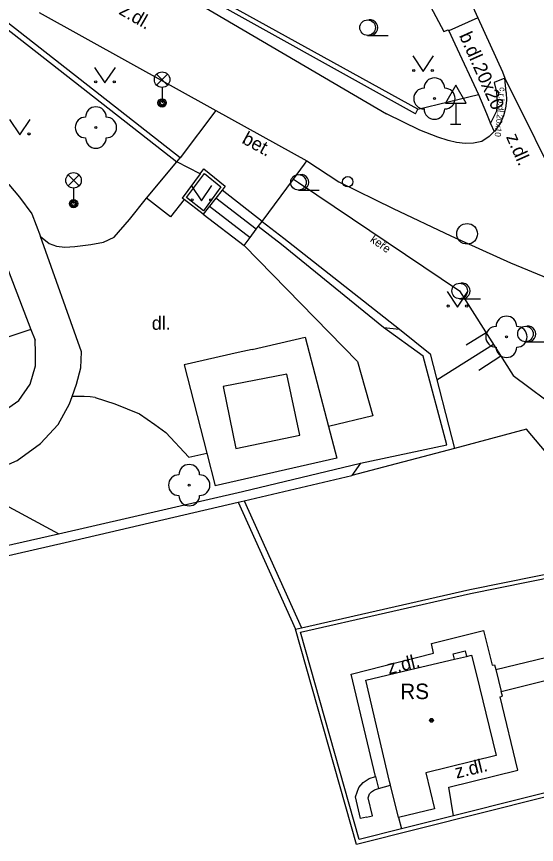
# Model space of a CAD drawing. Extents: x -595546 to -593986, y -1160845 to -1159202.
# Drawn here: x -595356.89 to -595331.77, y -1160440.78 to -1160400.75 of the extents above; entities that cross this region are included whole.
import ezdxf

# ---------------------------------------------------------------- set-up
doc = ezdxf.new("R2010")
doc.units = 0
for name, color, linetype in [('Level 22', 7, 'Continuous'), ('Level 27', 7, 'Continuous'), ('Level 31', 7, 'Continuous'), ('Level 33', 7, 'Continuous'), ('Level 34', 7, 'Continuous'), ('Level 36', 7, 'Continuous'), ('Level 39', 7, 'Continuous'), ('silnoproud - povrch.  znaky a  RIS  skut. velikost', 7, 'Continuous'), ('Specificka linie pasportu komunikaci', 7, 'Continuous'), ('TM - budovy zdene_ betonove - VP', 7, 'Continuous'), ('TM - chodniky - VP', 7, 'Continuous'), ('TM - horni hrana svahu', 7, 'Continuous'), ('TM - komunikace - VP', 7, 'Continuous'), ('TM - plot drateny_ kovovy - VP', 7, 'Continuous'), ('TM - plot dreveny - VP', 7, 'Continuous'), ('TM - plot zivy - VP', 7, 'Continuous'), ('TM - podezdivka plotu - VP', 7, 'Continuous'), ('TM - pomocna konstrukcni linie', 7, 'Continuous'), ('TM - popis objektu', 7, 'Continuous'), ('TM - popis povrchu', 7, 'Continuous'), ('TM - popis zelene', 7, 'Continuous'), ('TM - rozhrani mezi zpev. plochami mezi sebou - VP', 7, 'Continuous'), ('TM - rozhrani ploch obecne - VP', 7, 'Continuous'), ('TM - schody - VP', 7, 'Continuous'), ('TM - srafovani', 7, 'Continuous'), ('TM - zed operna - VP', 7, 'Continuous')]:
    doc.layers.add(name, color=color, linetype=linetype)

msp = doc.modelspace()

# ---------------------------------------------------------------- linework, layer by layer
at = {"layer": 'Level 22'}
for centre in [(-595336.7, -1160404.72), (-595353.06, -1160406.12), (-595333.22, -1160416.24), (-595348.55, -1160423.41)]:
    msp.add_circle(centre, 0.05, dxfattribs=at)
for centre, start, end in [((-595336.7, -1160404.22), 0, 180), ((-595337.2, -1160404.72), 90, 270), ((-595336.2, -1160404.72), 270, 90), ((-595353.06, -1160405.62), 0, 180), ((-595336.7, -1160405.22), 180, 0), ((-595353.56, -1160406.12), 90, 270), ((-595352.56, -1160406.12), 270, 90), ((-595353.06, -1160406.62), 180, 0), ((-595333.22, -1160415.74), 0, 180), ((-595333.72, -1160416.24), 90, 270), ((-595332.72, -1160416.24), 270, 90), ((-595333.22, -1160416.74), 180, 0), ((-595348.55, -1160422.91), 0, 180), ((-595349.05, -1160423.41), 90, 270), ((-595348.05, -1160423.41), 270, 90), ((-595348.55, -1160423.91), 180, 0)]:
    msp.add_arc(centre, 0.5, start, end, dxfattribs=at)
at = {"layer": 'Level 27'}
msp.add_circle((-595335.12, -1160411.26), 0.5, dxfattribs=at)
at = {"layer": 'Level 31'}
msp.add_circle((-595340.89, -1160408.74), 0.25, dxfattribs=at)
at = {"layer": 'Level 33'}
for p, q in [((-595350.125, -1160404.07), (-595349.595, -1160403.54)), ((-595350.125, -1160403.54), (-595349.595, -1160404.07)), ((-595349.86, -1160404.18), (-595349.86, -1160404.93)), ((-595354.405, -1160408.94), (-595353.875, -1160408.41)), ((-595354.405, -1160408.41), (-595353.875, -1160408.94)), ((-595354.14, -1160409.05), (-595354.14, -1160409.8))]:
    msp.add_line(p, q, dxfattribs=at)
for centre, radius in [((-595349.86, -1160403.805), 0.375), ((-595349.86, -1160404.93), 0.2), ((-595349.86, -1160404.93), 0.145), ((-595349.86, -1160404.93), 0.0876), ((-595354.14, -1160408.675), 0.375), ((-595354.14, -1160409.8), 0.2), ((-595354.14, -1160409.8), 0.145), ((-595354.14, -1160409.8), 0.0876)]:
    msp.add_circle(centre, radius, dxfattribs=at)
at = {"layer": 'Level 34'}
for p, q in [((-595335.67, -1160404.942), (-595335.67, -1160405.96)), ((-595335.92, -1160405.96), (-595335.42, -1160405.96))]:
    msp.add_line(p, q, dxfattribs=at)
msp.add_lwpolyline([(-595336.17, -1160404.942), (-595335.17, -1160404.942), (-595335.67, -1160404.076)], close=True, dxfattribs=at)
at = {"layer": 'Level 36'}
for p, q in [((-595339.93, -1160401.665), (-595338.93, -1160401.665)), ((-595343.27, -1160409.145), (-595342.27, -1160409.145)), ((-595335.48, -1160414.395), (-595334.48, -1160414.395)), ((-595332.3, -1160416.475), (-595331.3, -1160416.475))]:
    msp.add_line(p, q, dxfattribs=at)
for points in [[(-595337.75, -1160402.66), (-595337.25, -1160403.41), (-595336.75, -1160402.66)], [(-595353.12, -1160403.21), (-595352.62, -1160403.96), (-595352.12, -1160403.21)], [(-595357.24, -1160405.73), (-595356.74, -1160406.48), (-595356.24, -1160405.73)], [(-595348.46, -1160408.92), (-595347.96, -1160409.67), (-595347.46, -1160408.92)], [(-595336.09, -1160414.05), (-595335.59, -1160414.8), (-595335.09, -1160414.05)]]:
    msp.add_lwpolyline(points, dxfattribs=at)
for centre, radius in [((-595339.93, -1160401.29), 0.375), ((-595337.7, -1160403.36), 0.05), ((-595336.801, -1160403.36), 0.05), ((-595353.07, -1160403.91), 0.05), ((-595352.171, -1160403.91), 0.05), ((-595356.291, -1160406.43), 0.05), ((-595343.27, -1160408.77), 0.375), ((-595348.41, -1160409.62), 0.05), ((-595347.511, -1160409.62), 0.05), ((-595335.48, -1160414.02), 0.375), ((-595336.04, -1160414.75), 0.05), ((-595335.141, -1160414.75), 0.05), ((-595332.3, -1160416.1), 0.375)]:
    msp.add_circle(centre, radius, dxfattribs=at)
for centre in [(-595339.805, -1160401.29), (-595343.145, -1160408.77), (-595335.355, -1160414.02), (-595332.175, -1160416.1)]:
    msp.add_arc(centre, 0.375, 260.4059, 99.5941, dxfattribs=at)
at = {"layer": 'Level 39'}
for radius in [0.09, 0.0398]:
    msp.add_circle((-595336.84, -1160434.78), radius, dxfattribs=at)
at = {"layer": 'silnoproud - povrch.  znaky a  RIS  skut. velikost'}
msp.add_lwpolyline([(-595335.73, -1160431.83), (-595335.8, -1160431.57), (-595335.22, -1160431.42), (-595335.15, -1160431.69)], dxfattribs=at)
at = {"layer": 'Specificka linie pasportu komunikaci'}
for points in [[(-595348.02, -1160408.36), (-595349.15, -1160407.78)], [(-595339.16, -1160415.79), (-595338.39, -1160415.87)], [(-595353.1, -1160419.17), (-595353.34, -1160419.14), (-595353.62, -1160419.12), (-595353.8, -1160419.12), (-595354.03, -1160419.12), (-595354.21, -1160419.13)], [(-595340.28, -1160422.35), (-595340.69, -1160422.95)]]:
    msp.add_lwpolyline(points, dxfattribs=at)
at = {"layer": 'TM - budovy zdene_ betonove - VP'}
for points in [[(-595337.58, -1160432.26), (-595335.73, -1160431.83)], [(-595335.73, -1160431.83), (-595335.15, -1160431.69)], [(-595335.15, -1160431.69), (-595334.9, -1160431.63)], [(-595334.9, -1160431.63), (-595334.67, -1160432.58)], [(-595340.01, -1160432.83), (-595337.58, -1160432.26)], [(-595334.67, -1160432.58), (-595334.22, -1160434.44)], [(-595338.87, -1160437.73), (-595340.01, -1160432.83)], [(-595334.22, -1160434.44), (-595333.72, -1160436.48)], [(-595333.72, -1160436.48), (-595337.12, -1160437.31)], [(-595337.12, -1160437.31), (-595336.7, -1160439.06)], [(-595338.82, -1160437.92), (-595338.87, -1160437.73)], [(-595338.44, -1160439.48), (-595338.82, -1160437.92)], [(-595336.7, -1160439.06), (-595338.44, -1160439.48)]]:
    msp.add_lwpolyline(points, dxfattribs=at)
at = {"layer": 'TM - chodniky - VP'}
for points in [[(-595337.02, -1160400.02), (-595336.24, -1160401.47)], [(-595336.24, -1160401.47), (-595336.04, -1160401.4), (-595336, -1160401.44)], [(-595336, -1160401.44), (-595335.71, -1160402.08)], [(-595335.71, -1160402.08), (-595334.57, -1160404.53)], [(-595334.57, -1160404.53), (-595334.19, -1160405.44)], [(-595347.27, -1160405.29), (-595348.98, -1160407.58)], [(-595334.19, -1160405.44), (-595333.99, -1160405.93)], [(-595333.99, -1160405.93), (-595333.81, -1160406.31)], [(-595364.23, -1160407.36), (-595363.06, -1160407.11), (-595361.66, -1160407.04), (-595360.33, -1160407.21), (-595359.14, -1160407.65), (-595358.12, -1160408.2), (-595357.26, -1160408.88), (-595356.75, -1160409.49), (-595356.15, -1160410.29)], [(-595349.15, -1160407.78), (-595348.98, -1160407.58)], [(-595350.61, -1160409.54), (-595349.15, -1160407.78)], [(-595343.51, -1160408.61), (-595342.98, -1160407.89), (-595342.86, -1160407.73)], [(-595345.03, -1160410.66), (-595343.51, -1160408.61)], [(-595355.74, -1160411.39), (-595355.31, -1160411.72), (-595354.96, -1160411.86), (-595354.56, -1160411.9), (-595354.08, -1160411.87), (-595353.31, -1160411.78), (-595352.69, -1160411.66), (-595352.17, -1160411.42), (-595351.44, -1160410.56), (-595350.61, -1160409.54)], [(-595356.15, -1160410.29), (-595355.74, -1160411.39)], [(-595345.21, -1160410.9), (-595345.03, -1160410.66)], [(-595345.89, -1160411.82), (-595345.6, -1160411.43), (-595345.32, -1160411.04), (-595345.21, -1160410.9)], [(-595357.87, -1160411.58), (-595356.2, -1160415.88)], [(-595340.41, -1160417.43), (-595345.89, -1160411.82)], [(-595356.2, -1160415.88), (-595356, -1160416.4)], [(-595358.52, -1160420.22), (-595357.64, -1160419.92), (-595356.79, -1160419.31), (-595356.24, -1160418.52), (-595355.97, -1160417.64), (-595355.97, -1160416.99), (-595356, -1160416.4)], [(-595354.21, -1160419.13), (-595353.99, -1160418.52), (-595353.79, -1160417.74), (-595353.75, -1160416.97)], [(-595340.41, -1160417.43), (-595339.67, -1160420.06), (-595341.82, -1160420.57)], [(-595358.01, -1160422.72), (-595356.86, -1160422.21), (-595355.73, -1160421.39), (-595354.88, -1160420.47), (-595354.33, -1160419.48), (-595354.21, -1160419.13)], [(-595353.1, -1160419.17), (-595352.15, -1160419.48), (-595350.96, -1160419.96), (-595350.21, -1160420.47), (-595349.68, -1160420.87)], [(-595349.68, -1160420.87), (-595348.57, -1160422.06)], [(-595348.57, -1160422.06), (-595347.7, -1160421.87)]]:
    msp.add_lwpolyline(points, dxfattribs=at)
at = {"layer": 'TM - horni hrana svahu'}
for points in [[(-595343.51, -1160408.61), (-595343.27, -1160408.77)], [(-595335.48, -1160414.02), (-595332.9, -1160418.11)], [(-595332.9, -1160418.11), (-595330.56, -1160419.85)]]:
    msp.add_lwpolyline(points, dxfattribs=at)
at = {"layer": 'TM - komunikace - VP'}
for points in [[(-595337.63, -1160394.11), (-595334.6, -1160400.82)], [(-595348.94, -1160399.63), (-595339.02, -1160405.46)], [(-595355.8, -1160400.56), (-595347.27, -1160405.29)], [(-595334.6, -1160400.82), (-595333.41, -1160403.42), (-595333.29, -1160403.74)], [(-595333.24, -1160404.43), (-595333.29, -1160403.74)], [(-595333.24, -1160404.43), (-595333.22, -1160404.81), (-595333.26, -1160405.18), (-595333.36, -1160405.55), (-595333.51, -1160405.89)], [(-595347.27, -1160405.29), (-595342.86, -1160407.73)], [(-595337.4, -1160406.25), (-595339.02, -1160405.46)], [(-595333.51, -1160405.89), (-595333.75, -1160406.25), (-595333.81, -1160406.31)], [(-595336.54, -1160406.58), (-595337.4, -1160406.25)], [(-595333.81, -1160406.31), (-595334.06, -1160406.55), (-595334.41, -1160406.8)], [(-595336.03, -1160406.74), (-595336.54, -1160406.58)], [(-595334.41, -1160406.8), (-595334.81, -1160406.88), (-595335.22, -1160406.9), (-595335.63, -1160406.85), (-595336.03, -1160406.74)], [(-595342.86, -1160407.73), (-595341.32, -1160408.75)], [(-595341.32, -1160408.75), (-595338.69, -1160410.04)], [(-595338.69, -1160410.04), (-595335.9, -1160411.35)], [(-595335.9, -1160411.35), (-595333.03, -1160412.66)], [(-595333.03, -1160412.66), (-595331.18, -1160413.42)]]:
    msp.add_lwpolyline(points, dxfattribs=at)
at = {"layer": 'TM - plot drateny_ kovovy - VP'}
for points in [[(-595337.62, -1160405.46), (-595337.5, -1160405.24), (-595348.43, -1160399.19), (-595348.52, -1160398.84)], [(-595332.25, -1160420.71), (-595335.73, -1160421.63)], [(-595328.52, -1160425.14), (-595332.25, -1160420.71)], [(-595335.73, -1160421.63), (-595340.69, -1160422.95)], [(-595345.9, -1160424.17), (-595340.69, -1160422.95)], [(-595403.749, -1160437.257), (-595380.44, -1160432.07), (-595370.02, -1160429.73), (-595354.55, -1160426.18), (-595346.18, -1160424.24)], [(-595346.18, -1160424.24), (-595345.9, -1160424.17)], [(-595346.18, -1160424.24), (-595343.42, -1160430.37)], [(-595334.95, -1160428.65), (-595326.59, -1160426.96)], [(-595343.17, -1160430.52), (-595334.95, -1160428.65)], [(-595340.33, -1160440.54), (-595343.17, -1160430.52)], [(-595325.46, -1160436.8), (-595335.78, -1160439.39)], [(-595335.78, -1160439.39), (-595338.29, -1160440.03)], [(-595338.29, -1160440.03), (-595340.33, -1160440.54)]]:
    msp.add_lwpolyline(points, dxfattribs=at)
at = {"layer": 'TM - plot dreveny - VP'}
for points in [[(-595345.51, -1160416.85), (-595342.95, -1160416.26), (-595341.82, -1160420.57)], [(-595346.19, -1160417), (-595348.79, -1160417.6), (-595347.7, -1160421.87)], [(-595345.51, -1160416.85), (-595346.19, -1160417)], [(-595341.82, -1160420.57), (-595341.42, -1160422.1)], [(-595347.7, -1160421.87), (-595347.3, -1160423.44)], [(-595341.42, -1160422.1), (-595347.3, -1160423.44)]]:
    msp.add_lwpolyline(points, dxfattribs=at)
at = {"layer": 'TM - plot zivy - VP'}
msp.add_lwpolyline([(-595343.27, -1160408.77), (-595335.48, -1160414.02)], dxfattribs=at)
at = {"layer": 'TM - podezdivka plotu - VP'}
for points in [[(-595337.62, -1160405.46), (-595348.6, -1160399.33)], [(-595348.02, -1160408.36), (-595348.89, -1160409.53)], [(-595348.02, -1160408.36), (-595347.84, -1160408.12), (-595346.81, -1160408.95), (-595346.96, -1160409.15)], [(-595346.96, -1160409.15), (-595347.27, -1160409.54), (-595347.57, -1160409.92), (-595347.87, -1160410.31)], [(-595348.8, -1160409.6), (-595348.89, -1160409.53)], [(-595347.87, -1160410.31), (-595348.8, -1160409.6)], [(-595339.16, -1160415.79), (-595344.09, -1160411.77), (-595345.21, -1160410.9)], [(-595354.86, -1160425.77), (-595345.98, -1160423.72), (-595340.28, -1160422.35)], [(-595345.9, -1160424.17), (-595343.12, -1160430.3)], [(-595379.73, -1160431.39), (-595354.86, -1160425.77)], [(-595334.99, -1160428.45), (-595326.77, -1160426.79)], [(-595343.12, -1160430.3), (-595334.99, -1160428.45)], [(-595343.42, -1160430.37), (-595343.12, -1160430.3)], [(-595340.47, -1160440.78), (-595343.42, -1160430.37)], [(-595325.41, -1160436.99), (-595340.47, -1160440.78)]]:
    msp.add_lwpolyline(points, dxfattribs=at)
at = {"layer": 'TM - pomocna konstrukcni linie'}
for points in [[(-595337.5, -1160405.24), (-595334.57, -1160404.53)], [(-595338.44, -1160439.48), (-595338.29, -1160440.03)]]:
    msp.add_lwpolyline(points, dxfattribs=at)
at = {"layer": 'TM - rozhrani mezi zpev. plochami mezi sebou - VP'}
for points in [[(-595334.6, -1160400.82), (-595336, -1160401.44)], [(-595333.29, -1160403.74), (-595333.81, -1160403.95)], [(-595333.81, -1160403.95), (-595333.7, -1160404.41), (-595333.66, -1160404.87), (-595333.7, -1160405.34)], [(-595333.29, -1160403.74), (-595330.38, -1160409.6)], [(-595333.99, -1160405.93), (-595333.7, -1160405.34)], [(-595333.73, -1160432.32), (-595333.47, -1160433.38)], [(-595339.54, -1160437.5), (-595339.4, -1160438.08)]]:
    msp.add_lwpolyline(points, dxfattribs=at)
at = {"layer": 'TM - rozhrani ploch obecne - VP'}
for points in [[(-595348.98, -1160407.58), (-595357.7, -1160400.77), (-595365.59, -1160402.81), (-595365.53, -1160403.05), (-595357.76, -1160401.04), (-595349.15, -1160407.78)], [(-595345.03, -1160410.66), (-595346.96, -1160409.15)], [(-595348.8, -1160409.6), (-595349.46, -1160410.44), (-595350.61, -1160409.54)], [(-595347.87, -1160410.31), (-595345.89, -1160411.82)], [(-595345.03, -1160410.66), (-595343.98, -1160411.47), (-595338.39, -1160415.87)], [(-595356.2, -1160415.88), (-595362.47, -1160417.98), (-595363.77, -1160412.99), (-595359.54, -1160411.59), (-595357.87, -1160411.58)], [(-595353.75, -1160416.97), (-595355.74, -1160411.39)], [(-595338.39, -1160415.87), (-595336.91, -1160417.06)], [(-595336.91, -1160417.06), (-595335.73, -1160421.63)], [(-595343.84, -1160418.05), (-595346.91, -1160418.64)], [(-595343.2, -1160421), (-595343.84, -1160418.05)], [(-595346.91, -1160418.64), (-595346.3, -1160421.63)], [(-595346.3, -1160421.63), (-595343.2, -1160421)], [(-595354.86, -1160425.77), (-595358.04, -1160424.05), (-595369.83, -1160427.07), (-595380.2, -1160429.3), (-595379.73, -1160431.39)], [(-595340.73, -1160432.55), (-595336.75, -1160431.54), (-595336.84, -1160431.06), (-595334.33, -1160430.43), (-595333.91, -1160432.12)], [(-595333.73, -1160432.32), (-595326.34, -1160430.53)], [(-595333.47, -1160433.38), (-595325.61, -1160431.42)], [(-595333.91, -1160432.12), (-595333.8, -1160432.09), (-595333.73, -1160432.32)], [(-595339.54, -1160437.5), (-595340.73, -1160432.55)], [(-595335.78, -1160439.39), (-595336.01, -1160438.01), (-595332.67, -1160437.19), (-595333.53, -1160433.64), (-595333.41, -1160433.61)], [(-595333.41, -1160433.61), (-595333.47, -1160433.38)], [(-595339.99, -1160439.46), (-595340.28, -1160439.53), (-595340.52, -1160438.48), (-595340.35, -1160438.03), (-595340.14, -1160437.78), (-595339.85, -1160437.59), (-595339.54, -1160437.5)], [(-595339.4, -1160438.08), (-595338.82, -1160437.92)], [(-595339.99, -1160439.46), (-595339.7, -1160439.39), (-595339.9, -1160438.52), (-595339.83, -1160438.34), (-595339.74, -1160438.24), (-595339.59, -1160438.14), (-595339.4, -1160438.08)]]:
    msp.add_lwpolyline(points, dxfattribs=at)
at = {"layer": 'TM - schody - VP'}
for points in [[(-595345.32, -1160411.04), (-595347.27, -1160409.54)], [(-595347.57, -1160409.92), (-595345.6, -1160411.43)]]:
    msp.add_lwpolyline(points, dxfattribs=at)
at = {"layer": 'TM - srafovani'}
for points in [[(-595334.2, -1160416.05), (-595335.16, -1160416.65)], [(-595333.84, -1160416.61), (-595336.58, -1160418.34)], [(-595333.49, -1160417.18), (-595334.56, -1160417.86)]]:
    msp.add_lwpolyline(points, dxfattribs=at)
at = {"layer": 'TM - zed operna - VP'}
for points in [[(-595348.68, -1160409.5), (-595347.81, -1160408.34), (-595347.02, -1160408.98)], [(-595347.02, -1160408.98), (-595347.86, -1160410.14), (-595348.68, -1160409.5)], [(-595337.25, -1160417.18), (-595339.16, -1160415.79)], [(-595336.1, -1160421.46), (-595337.25, -1160417.18)], [(-595340.28, -1160422.35), (-595336.1, -1160421.46)]]:
    msp.add_lwpolyline(points, dxfattribs=at)

# ---------------------------------------------------------------- texts
at = {"layer": 'TM - popis objektu'}
msp.add_text('RS', height=0.75, rotation=0.34, dxfattribs=at).set_placement((-595338.35, -1160433.76))
at = {"layer": 'TM - popis povrchu'}
for s, height, rotation, p in [('z.dl.', 0.65, 330.0258, (-595351.99, -1160400.61)), ('b.dl.20x20', 0.65, 294.0584, (-595335.52, -1160401.67)), ('č.r.b.dl.20x10', 0.3, 264, (-595333.54, -1160404.16)), ('bet.', 0.65, 331.4456, (-595346.05, -1160406.85)), ('z.dl.', 0.65, 293.9123, (-595333.25, -1160406.57)), ('z.dl.', 0.65, 13.6159, (-595338.9, -1160432.56)), ('z.dl.', 0.65, 13.6159, (-595335.63, -1160437.6))]:
    msp.add_text(s, height=height, rotation=rotation, dxfattribs=at).set_placement(p)
msp.add_text('dl.', height=0.65, dxfattribs=at).set_placement((-595350.36, -1160415.9))
at = {"layer": 'TM - popis zelene'}
msp.add_text('keře', height=0.4, rotation=324.9153, dxfattribs=at).set_placement((-595339.84, -1160411.61))

doc.saveas('drawing.dxf')
